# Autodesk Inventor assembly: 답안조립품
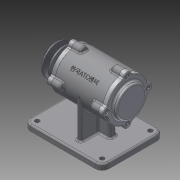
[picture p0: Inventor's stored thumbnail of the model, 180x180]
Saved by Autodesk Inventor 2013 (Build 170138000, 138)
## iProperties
Created: 2015-12
Part Number: 답안조립품
Document SubType Name: Assembly
Designer: cad8
Author: cad8
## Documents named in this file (11)
- C:\Documents and Settings\cad8\바탕 화면\451208V1005\답안조립품.iam
- C:\Documents and Settings\cad8\바탕 화면\451208V1005\본체.ipt
- C:\Documents and Settings\cad8\바탕 화면\451208V1005\커버.ipt
- C:\Documents and Settings\cad8\바탕 화면\451208V1005\커버2.ipt
- C:\Documents and Settings\cad8\바탕 화면\451208V1005\축.ipt
- C:\Documents and Settings\cad8\바탕 화면\451208V1005\베어링 6204.ipt
- C:\Documents and Settings\cad8\바탕 화면\451208V1005\오일실.ipt
- C:\Documents and Settings\cad8\바탕 화면\451208V1005\키(4 x 4 x 12).ipt
- C:\Documents and Settings\cad8\바탕 화면\451208V1005\V-벨트풀리.ipt
- C:\Documents and Settings\cad8\바탕 화면\451208V1005\너트 M12x1.25.ipt
- C:\Documents and Settings\cad8\바탕 화면\451208V1005\볼트 M4 x 12.ipt
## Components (6 placed, 5 different names)
1. KS B 2023 6204 - 20 x 47 x 14:1
2. KS B 2023 6204 - 20 x 47 x 14:2
3. KS B 2804 D D - 20 32 8:1
4. KS B 1311 (I) 4 x 4 x 12:1
5. V-벨트풀리:1
6. KS B 1012 클래스 1 일반 - 미터 M12x1.25:1
